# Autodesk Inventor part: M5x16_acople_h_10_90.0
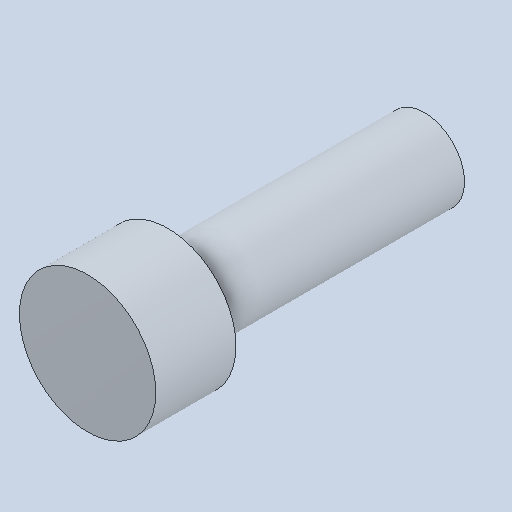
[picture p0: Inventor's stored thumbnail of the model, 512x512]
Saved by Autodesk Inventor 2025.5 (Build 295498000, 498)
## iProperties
Created: 2026-10
Part Number: M5x16_acople_h_10_90.0
Material: Genérico
Document SubType Name: Modeling
Designer: Luis M
Density: 1 g/cm^3
Appearance: Valor por defecto
Author: Luis M
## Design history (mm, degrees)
feature "Base1"
node "Sólido1"
